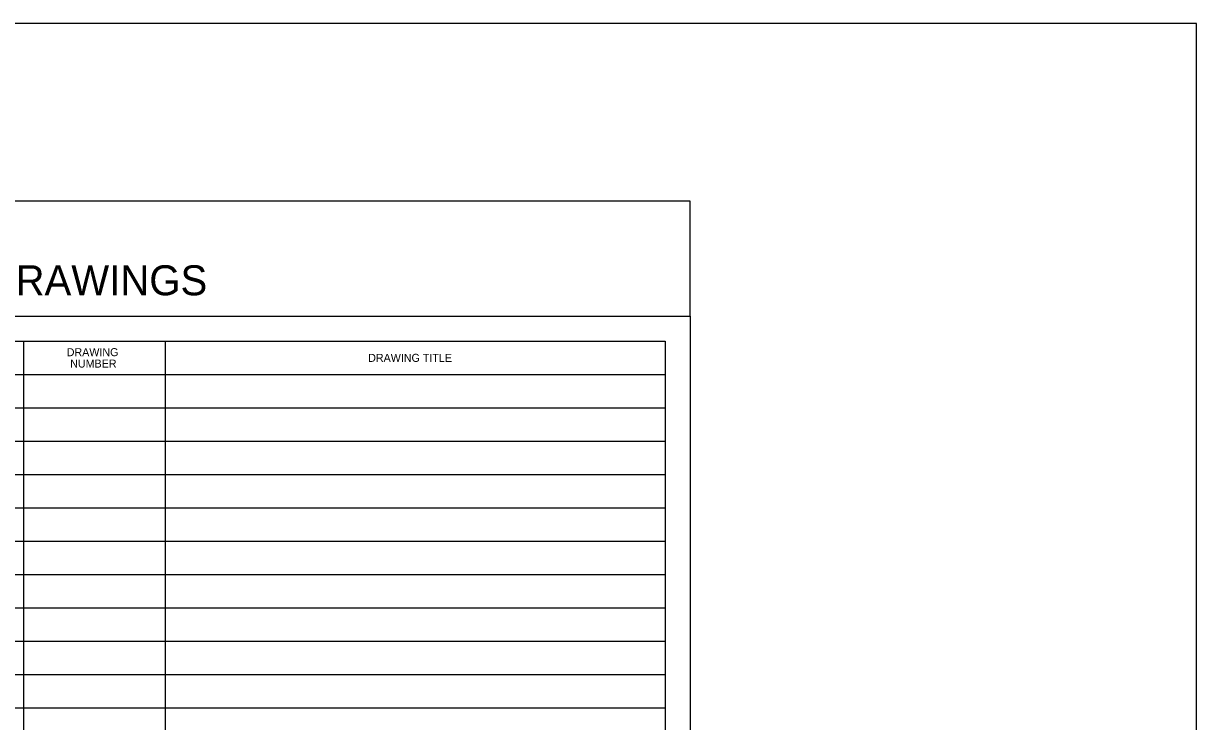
# Model space of a CAD drawing. Extents: x 0 to 31.8, y -0.5 to 20.8.
# Drawn here: x 14.16 to 31.75, y 10.27 to 20.75 of the extents above; entities that cross this region are included whole.
import ezdxf

# ---------------------------------------------------------------- set-up
doc = ezdxf.new("R2010")
doc.units = 0
for name, color, linetype in [('CT_Border_Perimeter_Shape', 7, 'Continuous'), ('CT_Text', 7, 'Continuous'), ('CT_TSH_Annotation_Locked', 7, 'Continuous'), ('CT_TSH_Line_Work_Major', 7, 'Continuous'), ('CT_TSH_Line_Work_Minor', 7, 'Continuous')]:
    doc.layers.add(name, color=color, linetype=linetype)

msp = doc.modelspace()

# ---------------------------------------------------------------- linework, layer by layer
at = {"layer": 'CT_Border_Perimeter_Shape'}
msp.add_lwpolyline([(0, 0), (31.75, 0), (31.75, 20.75), (0, 20.75)], close=True, dxfattribs=at)
at = {"layer": 'CT_TSH_Line_Work_Major'}
for p, q in [((4.156, 16.357), (24.156, 16.357)), ((24.156, 16.357), (24.156, 5.107))]:
    msp.add_line(p, q, dxfattribs=at)
msp.add_lwpolyline([(4.156, 16.357), (24.156, 16.357), (24.156, 18.084), (4.156, 18.084)], close=True, dxfattribs=at)
at = {"layer": 'CT_TSH_Line_Work_Minor'}
for p, q in [((4.531, 15.982), (14.156, 15.982)), ((14.156, 15.982), (14.156, 5.482)), ((14.156, 15.982), (23.781, 15.982)), ((16.281, 15.982), (16.281, 5.482)), ((23.781, 15.982), (23.781, 5.482)), ((4.531, 15.482), (14.156, 15.482)), ((14.156, 15.482), (23.781, 15.482)), ((4.531, 14.982), (14.156, 14.982)), ((14.156, 14.982), (23.781, 14.982)), ((4.531, 14.482), (14.156, 14.482)), ((14.156, 14.482), (23.781, 14.482)), ((4.531, 13.982), (14.156, 13.982)), ((14.156, 13.982), (23.781, 13.982)), ((4.531, 13.482), (14.156, 13.482)), ((14.156, 13.482), (23.781, 13.482)), ((4.531, 12.982), (14.156, 12.982)), ((14.156, 12.982), (23.781, 12.982)), ((4.531, 12.482), (14.156, 12.482)), ((14.156, 12.482), (23.781, 12.482)), ((4.531, 11.982), (14.156, 11.982)), ((14.156, 11.982), (23.781, 11.982)), ((4.531, 11.482), (14.156, 11.482)), ((14.156, 11.482), (23.781, 11.482)), ((4.531, 10.982), (14.156, 10.982)), ((14.156, 10.982), (23.781, 10.982)), ((4.531, 10.482), (14.156, 10.482)), ((14.156, 10.482), (23.781, 10.482))]:
    msp.add_line(p, q, dxfattribs=at)

# ---------------------------------------------------------------- texts
at = {"layer": 'CT_Text'}
msp.add_text('DRAWING TITLE', height=0.12, dxfattribs=at).set_placement((19.326, 15.672))
at = {"layer": 'CT_TSH_Annotation_Locked'}
for s, height, p in [('INDEX OF DRAWINGS', 0.45, (10.594, 16.671)), ('DRAWING', 0.12, (14.805, 15.757)), ('NUMBER', 0.12, (14.857, 15.586))]:
    msp.add_text(s, height=height, dxfattribs=at).set_placement(p)

doc.saveas('drawing.dxf')
